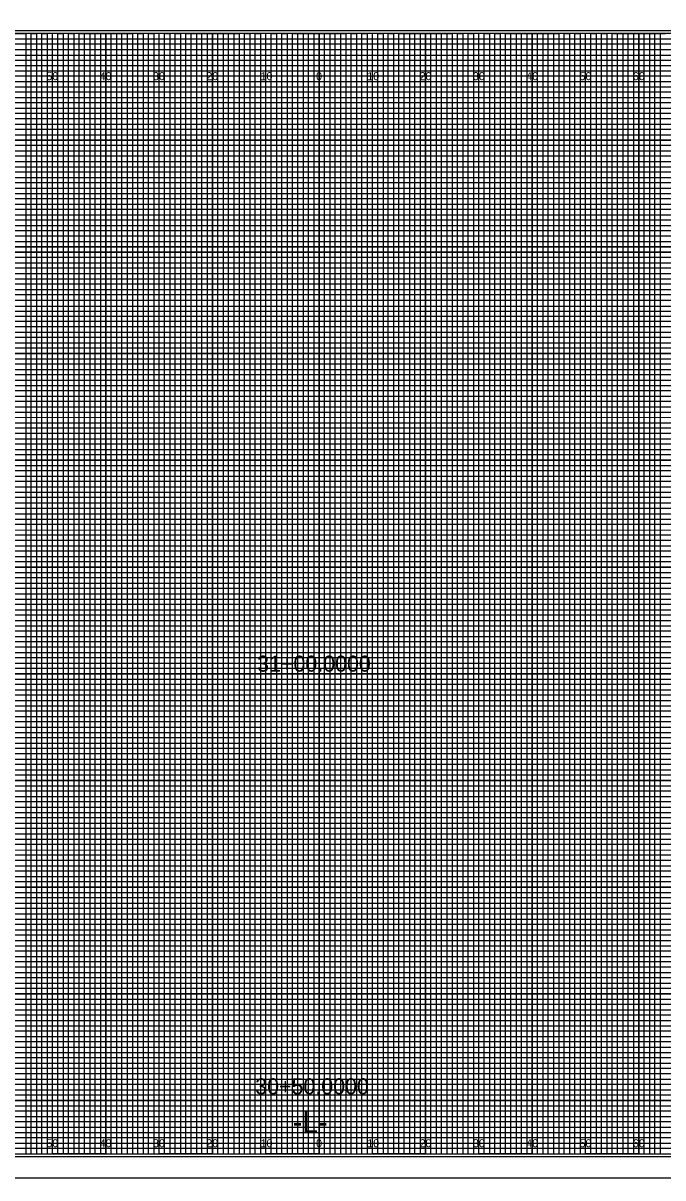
# Model space of a CAD drawing. Extents: x -419 to 4739, y -630 to 13534.
# Drawn here: x 594.1 to 714.1, y 2628 to 2844.5 of the extents above; entities that cross this region are included whole.
import ezdxf

# ---------------------------------------------------------------- set-up
doc = ezdxf.new("R2010")
doc.units = 0
for name, color, linetype in [('Old_Level_62', 7, 'Continuous'), ('Pattern 18', 7, 'Continuous'), ('Pattern 4', 7, 'Continuous'), ('Pattern 5', 7, 'Continuous'), ('Prop Dimension', 7, 'Continuous'), ('Prop Horizontal Alignment', 7, 'Continuous'), ('Prop PHM White Shape', 7, 'Continuous'), ('Raster_Level_0', 7, 'Continuous'), ('Scratch_Level_0', 7, 'Continuous'), ('Scratch_Level_2', 7, 'Continuous'), ('Scratch_Level_3', 7, 'Continuous'), ('Scratch_Level_5', 7, 'Continuous')]:
    doc.layers.add(name, color=color, linetype=linetype)

msp = doc.modelspace()

# ---------------------------------------------------------------- linework, layer by layer
at = {"layer": 'Old_Level_62'}
msp.add_lwpolyline([(809.58, 2842.54), (489.58, 2842.54), (489.58, 2632.54), (809.58, 2632.54)], close=True, dxfattribs=at)
at = {"layer": 'Pattern 18'}
msp.add_lwpolyline([(476.18, 2628.04), (812.88, 2628.04), (812.88, 2847.04), (476.18, 2847.04)], close=True, dxfattribs=at)
at = {"layer": 'Pattern 4'}
for p, q in [((489.58, 2841.54), (749.58, 2841.54)), ((749.58, 2840.52), (489.58, 2840.52)), ((489.58, 2839.54), (749.58, 2839.54)), ((749.58, 2838.43), (489.58, 2838.43)), ((489.58, 2836.54), (809.58, 2836.54))]:
    msp.add_line(p, q, dxfattribs=at)
for points in [[(489.58, 2835.54), (759.58, 2835.54), (809.58, 2835.54), (809.58, 2834.54), (489.58, 2834.54)], [(489.58, 2833.54), (809.58, 2833.54), (809.58, 2831.54), (489.58, 2831.54)], [(489.58, 2830.54), (809.58, 2830.54), (809.58, 2829.54), (489.58, 2829.52)], [(489.58, 2828.54), (809.58, 2828.54), (809.58, 2826.54), (489.58, 2826.54)], [(489.58, 2825.54), (809.58, 2825.54), (809.58, 2824.54), (489.58, 2824.54)], [(489.58, 2823.54), (809.58, 2823.54), (809.58, 2821.54), (489.58, 2821.54)], [(489.58, 2820.54), (809.58, 2820.54), (809.58, 2819.54), (489.58, 2819.54)], [(489.58, 2818.54), (809.58, 2818.54), (809.58, 2816.54), (489.58, 2816.54)], [(489.58, 2815.54), (809.58, 2815.54), (809.58, 2814.54), (489.58, 2814.54)], [(489.58, 2813.54), (809.58, 2813.54), (809.58, 2811.54), (489.58, 2811.54)], [(489.58, 2810.54), (809.58, 2810.54), (809.58, 2809.54), (489.58, 2809.54)], [(489.58, 2808.54), (809.58, 2808.54), (809.58, 2806.49), (809.58, 2805.54), (809.58, 2804.54), (489.58, 2804.54)], [(489.58, 2806.54), (809.58, 2806.54), (809.58, 2805.54), (489.58, 2805.54)], [(489.58, 2803.54), (809.58, 2803.54), (809.58, 2801.54), (489.58, 2801.57)], [(489.58, 2801.57), (809.58, 2801.54), (809.58, 2800.54), (489.58, 2800.54)], [(489.58, 2799.54), (809.58, 2799.54), (809.58, 2798.54), (489.58, 2798.54)], [(489.58, 2796.54), (809.58, 2796.54), (809.58, 2795.54), (489.58, 2795.54)], [(489.58, 2794.54), (809.58, 2794.54), (809.58, 2793.54), (489.58, 2793.54)], [(489.51, 2791.43), (809.58, 2791.43), (809.58, 2790.42), (489.51, 2790.42)], [(489.58, 2789.54), (809.58, 2789.54), (809.58, 2788.54), (489.58, 2788.54)], [(489.58, 2786.54), (809.58, 2786.54), (809.58, 2785.54), (489.58, 2785.54)], [(489.58, 2784.54), (809.58, 2784.54), (809.58, 2783.54), (489.58, 2783.54)], [(489.58, 2781.54), (809.58, 2781.54), (809.58, 2780.54), (489.58, 2780.54)], [(489.58, 2779.54), (809.58, 2779.54), (809.58, 2778.54), (489.58, 2778.54)], [(489.58, 2776.54), (809.58, 2776.54), (809.58, 2775.54), (489.58, 2775.54)], [(489.58, 2774.54), (809.58, 2774.54), (809.58, 2773.54), (489.58, 2773.54)], [(489.58, 2771.54), (809.58, 2771.54), (809.57, 2770.52), (489.58, 2770.54)], [(489.58, 2769.54), (809.58, 2769.54), (809.58, 2768.54), (489.58, 2768.54)], [(489.58, 2766.54), (809.58, 2766.54), (809.58, 2765.54), (489.58, 2765.54)], [(489.58, 2764.54), (809.58, 2764.54), (809.58, 2763.54), (489.58, 2763.54)], [(489.58, 2761.54), (809.58, 2761.54), (809.58, 2760.54), (489.58, 2760.54)], [(489.58, 2759.54), (809.58, 2759.54), (809.58, 2758.54), (489.58, 2758.54)], [(489.58, 2756.54), (809.58, 2756.54), (809.58, 2755.54), (489.58, 2755.54)], [(489.58, 2754.54), (809.58, 2754.54), (809.58, 2753.54), (489.58, 2753.54)], [(489.58, 2751.54), (809.58, 2751.54), (809.58, 2750.54), (489.58, 2750.54)], [(489.58, 2749.53), (809.65, 2749.45), (809.58, 2748.54), (489.58, 2748.54)], [(489.58, 2746.54), (809.58, 2746.54), (809.58, 2745.54), (489.58, 2745.54)], [(489.58, 2744.54), (809.58, 2744.54), (809.58, 2743.54), (489.58, 2743.54)], [(489.58, 2741.54), (809.58, 2741.54), (809.58, 2740.54), (489.58, 2740.54)], [(489.58, 2739.54), (809.58, 2739.54), (809.58, 2738.54), (489.58, 2738.54)], [(489.58, 2736.54), (809.58, 2736.54), (809.58, 2735.54), (489.58, 2735.54)], [(489.58, 2734.54), (809.58, 2734.54), (809.58, 2733.54), (489.58, 2733.54)], [(489.58, 2731.54), (809.58, 2731.54), (809.58, 2730.54), (489.58, 2730.54)], [(489.58, 2729.54), (809.58, 2729.54), (809.58, 2728.54), (489.58, 2728.54)], [(489.58, 2726.54), (809.58, 2726.54), (809.58, 2725.54), (489.58, 2725.54)], [(489.58, 2724.54), (809.58, 2724.54), (809.58, 2723.54), (489.58, 2723.54)], [(489.58, 2721.54), (809.58, 2721.54), (809.58, 2720.54), (489.58, 2720.54)], [(489.58, 2719.54), (809.58, 2719.54), (809.58, 2718.54), (489.58, 2718.54)], [(489.58, 2716.54), (809.58, 2716.54), (809.58, 2715.54), (489.58, 2715.54)], [(489.58, 2714.54), (809.58, 2714.54), (809.58, 2713.54), (489.58, 2713.54)], [(489.58, 2711.54), (809.58, 2711.54), (809.57, 2710.52), (489.58, 2710.54)], [(489.58, 2709.54), (809.58, 2709.54), (809.58, 2708.54), (489.58, 2708.54)], [(489.58, 2706.54), (809.58, 2706.54), (809.58, 2705.54), (489.58, 2705.54)], [(489.58, 2704.54), (809.58, 2704.54), (809.58, 2703.54), (489.58, 2703.54)], [(489.58, 2701.54), (809.58, 2701.54), (809.58, 2700.54), (489.58, 2700.54)], [(489.58, 2699.54), (809.58, 2699.54), (809.58, 2698.54), (489.58, 2698.54)], [(489.58, 2696.54), (809.58, 2696.54), (809.58, 2695.54), (489.58, 2695.54)], [(489.58, 2694.54), (809.58, 2694.54), (809.58, 2693.54), (489.58, 2693.54)], [(489.58, 2691.54), (809.58, 2691.54), (809.58, 2690.54), (489.58, 2690.54)], [(489.58, 2689.53), (809.65, 2689.45), (809.58, 2688.54), (489.58, 2688.54)], [(489.58, 2686.54), (809.58, 2686.54), (809.58, 2685.54), (489.58, 2685.54)], [(489.58, 2684.54), (809.58, 2684.54), (809.58, 2683.54), (489.58, 2683.54)], [(489.58, 2681.54), (809.58, 2681.54), (809.58, 2680.54), (489.58, 2680.54)], [(489.58, 2679.54), (809.58, 2679.54), (809.58, 2678.54), (489.58, 2678.54)], [(489.58, 2676.54), (809.58, 2676.54), (809.58, 2675.54), (489.58, 2675.54)], [(489.58, 2674.54), (809.58, 2674.54), (809.58, 2673.54), (489.58, 2673.54)], [(489.58, 2671.54), (809.58, 2671.54), (809.58, 2670.54), (489.58, 2670.54)], [(489.58, 2669.54), (809.58, 2669.54), (809.58, 2668.54), (489.58, 2668.54)], [(489.58, 2666.54), (809.58, 2666.54), (809.58, 2665.54), (489.58, 2665.54)], [(489.58, 2664.54), (809.58, 2664.54), (809.58, 2663.54), (489.58, 2663.54)], [(489.58, 2661.54), (809.58, 2661.54), (809.58, 2660.54), (489.58, 2660.54)], [(489.58, 2659.54), (809.58, 2659.54), (809.58, 2658.54), (489.58, 2658.54)], [(489.58, 2656.54), (809.58, 2656.54), (809.58, 2655.54), (489.58, 2655.54)], [(489.58, 2654.54), (809.58, 2654.54), (809.58, 2653.54), (489.58, 2653.54)], [(489.58, 2651.54), (809.58, 2651.54), (809.58, 2650.54), (489.58, 2650.54)], [(489.58, 2649.54), (809.58, 2649.54), (809.58, 2648.54), (489.58, 2648.54)], [(489.58, 2646.54), (809.58, 2646.54), (809.58, 2645.54), (489.58, 2645.54)], [(489.58, 2644.54), (809.58, 2644.54), (809.58, 2643.54), (489.58, 2643.54)], [(489.58, 2641.54), (809.58, 2641.54), (809.58, 2640.54), (489.58, 2640.54)], [(489.58, 2639.54), (809.58, 2639.54), (809.58, 2638.54), (489.58, 2638.54)], [(489.58, 2636.54), (809.58, 2636.54), (809.58, 2635.54), (489.58, 2635.54)], [(489.58, 2634.54), (809.58, 2634.54), (809.58, 2633.54), (489.58, 2633.54)]]:
    msp.add_lwpolyline(points, dxfattribs=at)
at = {"layer": 'Pattern 5'}
msp.add_line((476.18, 2628.04), (812.88, 2628.04), dxfattribs=at)
at = {"layer": 'Prop Dimension'}
for points in [[(594.58, 2632.54), (595.58, 2632.54), (595.58, 2842.54), (596.58, 2842.54), (596.58, 2632.54)], [(596.58, 2632.54), (597.58, 2632.54), (597.58, 2842.54), (598.58, 2842.54), (598.58, 2632.54)], [(599.58, 2632.54), (600.58, 2632.54), (600.58, 2842.54), (601.58, 2842.54), (601.58, 2632.54)], [(601.58, 2632.54), (602.58, 2632.54), (602.58, 2842.54), (603.58, 2842.54), (603.58, 2632.54)], [(604.58, 2632.54), (605.58, 2632.54), (605.58, 2842.54), (606.58, 2842.54), (606.58, 2632.54)], [(606.58, 2632.54), (607.58, 2632.54), (607.58, 2842.54), (608.58, 2842.54), (608.58, 2632.54)], [(609.58, 2632.54), (610.58, 2632.54), (610.58, 2842.54), (611.58, 2842.54), (611.58, 2632.54)], [(611.58, 2632.54), (612.58, 2632.54), (612.58, 2842.54), (613.58, 2842.54), (613.58, 2632.54)], [(614.58, 2632.54), (615.58, 2632.54), (615.58, 2842.54), (616.58, 2842.54), (616.58, 2632.54)], [(616.58, 2632.54), (617.58, 2632.54), (617.58, 2842.54), (618.58, 2842.54), (618.58, 2632.54)], [(619.58, 2632.54), (620.58, 2632.54), (620.58, 2842.54), (621.58, 2842.54), (621.58, 2632.54)], [(621.58, 2632.54), (622.58, 2632.54), (622.58, 2842.54), (623.58, 2842.54), (623.58, 2632.54)], [(624.58, 2632.54), (625.58, 2632.54), (625.58, 2842.54), (626.58, 2842.54), (626.58, 2632.54)], [(626.58, 2632.54), (627.58, 2632.54), (627.58, 2842.54), (628.58, 2842.54), (628.58, 2632.54)], [(629.58, 2632.54), (630.58, 2632.54), (630.58, 2842.54), (631.58, 2842.54), (631.58, 2632.54)], [(631.58, 2632.54), (632.58, 2632.54), (632.58, 2842.54), (633.58, 2842.54), (633.58, 2632.54)], [(634.58, 2632.54), (635.58, 2632.54), (635.58, 2842.54), (636.58, 2842.54), (636.58, 2632.54)], [(636.58, 2632.54), (637.58, 2632.54), (637.58, 2842.54), (638.58, 2842.54), (638.58, 2632.54)], [(639.58, 2632.54), (640.58, 2632.54), (640.58, 2842.54), (641.58, 2842.54), (641.58, 2632.54)], [(641.58, 2632.54), (642.58, 2632.54), (642.58, 2842.54), (643.58, 2842.54), (643.58, 2632.54)], [(644.58, 2632.54), (645.58, 2632.54), (645.58, 2842.54), (646.58, 2842.54), (646.58, 2632.54)], [(646.58, 2632.54), (647.58, 2632.54), (647.58, 2842.54), (648.58, 2842.54), (648.58, 2632.54)], [(649.58, 2632.54), (650.58, 2632.54), (650.58, 2842.54), (651.58, 2842.54), (651.58, 2632.54)], [(651.58, 2632.54), (652.58, 2632.54), (652.58, 2842.54), (653.58, 2842.54), (653.58, 2632.54)], [(654.58, 2632.54), (655.58, 2632.54), (655.58, 2842.54), (656.58, 2842.54), (656.58, 2632.54)], [(656.58, 2632.54), (657.58, 2632.54), (657.58, 2842.54), (658.58, 2842.54), (658.58, 2632.54)], [(659.58, 2632.54), (660.58, 2632.54), (660.58, 2842.54), (661.58, 2842.54), (661.58, 2632.54)], [(661.58, 2632.54), (662.58, 2632.54), (662.58, 2842.54), (663.58, 2842.54), (663.58, 2632.54)], [(664.58, 2632.54), (665.58, 2632.54), (665.58, 2842.54), (666.58, 2842.54), (666.58, 2632.54)], [(666.58, 2632.54), (667.58, 2632.54), (667.58, 2842.54), (668.58, 2842.54), (668.58, 2632.54)], [(669.58, 2632.54), (670.58, 2632.54), (670.58, 2842.54), (671.58, 2842.54), (671.58, 2632.54)], [(671.58, 2632.54), (672.58, 2632.54), (672.58, 2842.54), (673.58, 2842.54), (673.58, 2632.54)], [(674.58, 2632.54), (675.58, 2632.54), (675.58, 2842.54), (676.58, 2842.54), (676.58, 2632.54)], [(676.58, 2632.54), (677.58, 2632.54), (677.58, 2842.54), (678.58, 2842.54), (678.58, 2632.54)], [(679.58, 2632.54), (680.58, 2632.54), (680.58, 2842.54), (681.58, 2842.54), (681.58, 2632.54)], [(681.58, 2632.54), (682.58, 2632.54), (682.58, 2842.54), (683.58, 2842.54), (683.58, 2632.54)], [(684.58, 2632.54), (685.58, 2632.54), (685.58, 2842.54), (686.58, 2842.54), (686.58, 2632.54)], [(686.58, 2632.54), (687.58, 2632.54), (687.58, 2842.54), (688.58, 2842.54), (688.58, 2632.54)], [(689.58, 2632.54), (690.58, 2632.54), (690.58, 2842.54), (691.58, 2842.54), (691.58, 2632.54)], [(691.58, 2632.54), (692.58, 2632.54), (692.58, 2842.54), (693.58, 2842.54), (693.58, 2632.54)], [(694.58, 2632.54), (695.58, 2632.54), (695.58, 2842.54), (696.58, 2842.54), (696.58, 2632.54)], [(696.58, 2632.54), (697.58, 2632.54), (697.58, 2842.54), (698.58, 2842.54), (698.58, 2632.54)], [(699.58, 2632.54), (700.58, 2632.54), (700.58, 2842.54), (701.58, 2842.54), (701.58, 2632.54)], [(701.58, 2632.54), (702.58, 2632.54), (702.58, 2842.54), (703.58, 2842.54), (703.58, 2632.54)], [(704.58, 2632.54), (705.58, 2632.54), (705.58, 2842.54), (706.58, 2842.54), (706.58, 2632.54)], [(706.58, 2632.54), (707.58, 2632.54), (707.58, 2842.54), (708.58, 2842.54), (708.58, 2632.54)], [(709.58, 2632.54), (710.58, 2632.54), (710.58, 2842.54), (711.58, 2842.54), (711.58, 2632.54)], [(711.58, 2632.54), (712.58, 2632.54), (712.58, 2842.54), (713.58, 2842.54), (713.58, 2632.54)]]:
    msp.add_lwpolyline(points, dxfattribs=at)
at = {"layer": 'Prop Horizontal Alignment'}
for points in [[(584.58, 2842.54), (594.58, 2842.54), (594.58, 2632.54), (604.58, 2632.54), (604.58, 2842.54), (614.58, 2842.54), (614.58, 2632.54), (624.58, 2632.54), (624.58, 2842.54), (634.58, 2842.54), (634.58, 2632.54), (644.58, 2632.54), (644.58, 2842.54), (654.58, 2842.54), (654.58, 2632.54), (664.58, 2632.54), (664.58, 2842.54), (674.58, 2842.54), (674.58, 2632.54), (684.58, 2632.54), (684.58, 2842.54), (694.58, 2842.54), (694.58, 2632.54), (704.58, 2632.54), (704.58, 2842.54), (714.58, 2842.54)], [(489.58, 2837.54), (764.58, 2837.54)], [(489.58, 2817.54), (809.58, 2817.54), (809.58, 2827.54), (489.58, 2827.54)], [(489.58, 2797.54), (809.58, 2797.54), (809.58, 2807.54), (489.58, 2807.54)], [(489.58, 2777.54), (809.58, 2777.54), (809.58, 2787.54), (489.58, 2787.54)], [(489.58, 2757.54), (809.58, 2757.54), (809.58, 2767.54), (489.58, 2767.54)], [(489.58, 2737.54), (809.58, 2737.54), (809.58, 2747.54), (489.58, 2747.54)], [(489.58, 2717.54), (809.58, 2717.54), (809.58, 2727.54), (489.58, 2727.54)], [(489.58, 2697.54), (809.58, 2697.54), (809.58, 2707.54), (489.58, 2707.54)], [(489.58, 2677.54), (809.58, 2677.54), (809.58, 2687.54), (489.58, 2687.54)], [(489.58, 2657.54), (809.58, 2657.54), (809.58, 2667.54), (489.58, 2667.54)], [(489.58, 2637.54), (809.58, 2637.54), (809.58, 2647.54), (489.58, 2647.54)]]:
    msp.add_lwpolyline(points, dxfattribs=at)
at = {"layer": 'Scratch_Level_0'}
for p, q in [((599.58, 2632.54), (599.58, 2842.54)), ((609.58, 2632.54), (609.58, 2842.54)), ((619.58, 2632.54), (619.58, 2842.54)), ((629.58, 2632.54), (629.58, 2842.54)), ((639.58, 2632.54), (639.58, 2842.54)), ((649.58, 2632.54), (649.58, 2842.54)), ((659.58, 2632.54), (659.58, 2842.54)), ((669.58, 2632.54), (669.58, 2842.54)), ((679.58, 2632.54), (679.58, 2842.54)), ((689.58, 2632.54), (689.58, 2842.54)), ((699.58, 2632.54), (699.58, 2842.54)), ((709.58, 2632.54), (709.58, 2842.54)), ((489.58, 2832.54), (809.58, 2832.54)), ((489.58, 2822.54), (809.58, 2822.54)), ((489.58, 2812.54), (809.58, 2812.54)), ((489.58, 2802.54), (809.58, 2802.54)), ((489.58, 2792.54), (809.58, 2792.54)), ((489.58, 2782.54), (809.58, 2782.54)), ((489.58, 2772.54), (809.58, 2772.54)), ((489.58, 2762.54), (809.58, 2762.54)), ((489.58, 2752.54), (809.58, 2752.54)), ((489.58, 2742.54), (809.58, 2742.54)), ((489.58, 2732.54), (809.58, 2732.54)), ((489.58, 2722.54), (809.58, 2722.54)), ((489.58, 2712.54), (809.58, 2712.54)), ((489.58, 2702.54), (809.58, 2702.54)), ((489.58, 2692.54), (809.58, 2692.54)), ((489.58, 2682.54), (809.58, 2682.54)), ((489.58, 2672.54), (809.58, 2672.54)), ((489.58, 2662.54), (809.58, 2662.54)), ((489.58, 2652.54), (809.58, 2652.54)), ((489.58, 2642.54), (809.58, 2642.54))]:
    msp.add_line(p, q, dxfattribs=at)
at = {"layer": 'Scratch_Level_3'}
for p, q in [((599.58, 2842.54), (589.58, 2842.54)), ((599.58, 2632.54), (599.58, 2842.54)), ((619.58, 2842.54), (609.58, 2842.54)), ((609.58, 2842.54), (609.58, 2632.54)), ((619.58, 2632.54), (619.58, 2842.54)), ((639.58, 2842.54), (629.58, 2842.54)), ((629.58, 2842.54), (629.58, 2632.54)), ((639.58, 2632.54), (639.58, 2842.54)), ((659.58, 2842.54), (649.58, 2842.54)), ((649.58, 2842.54), (649.58, 2632.54)), ((659.58, 2632.54), (659.58, 2842.54)), ((679.58, 2842.54), (669.58, 2842.54)), ((669.58, 2842.54), (669.58, 2632.54)), ((679.58, 2632.54), (679.58, 2842.54)), ((699.58, 2842.54), (689.58, 2842.54)), ((689.58, 2842.54), (689.58, 2632.54)), ((699.58, 2632.54), (699.58, 2842.54)), ((719.58, 2842.54), (709.58, 2842.54)), ((709.58, 2842.54), (709.58, 2632.54)), ((609.58, 2632.54), (599.58, 2632.54)), ((629.58, 2632.54), (619.58, 2632.54)), ((649.58, 2632.54), (639.58, 2632.54)), ((669.58, 2632.54), (659.58, 2632.54)), ((689.58, 2632.54), (679.58, 2632.54)), ((709.58, 2632.54), (699.58, 2632.54))]:
    msp.add_line(p, q, dxfattribs=at)
for points in [[(489.58, 2832.54), (809.58, 2832.54), (809.58, 2822.54), (489.58, 2822.54)], [(489.58, 2812.54), (809.58, 2812.54), (809.58, 2802.54), (489.58, 2802.54)], [(489.58, 2792.54), (809.58, 2792.54), (809.58, 2782.54), (489.58, 2782.54)], [(489.58, 2772.54), (809.58, 2772.54), (809.58, 2762.54), (489.58, 2762.54)], [(489.58, 2752.54), (809.58, 2752.54), (809.58, 2742.54), (489.58, 2742.54)], [(489.58, 2732.54), (809.58, 2732.54), (809.58, 2722.54), (489.58, 2722.54)], [(489.58, 2712.54), (809.58, 2712.54), (809.58, 2702.54), (489.58, 2702.54)], [(489.58, 2692.54), (809.58, 2692.54), (809.58, 2682.54), (489.58, 2682.54)], [(489.58, 2672.54), (809.58, 2672.54), (809.58, 2662.54), (489.58, 2662.54)], [(489.58, 2652.54), (809.58, 2652.54), (809.58, 2642.54), (489.58, 2642.54)]]:
    msp.add_lwpolyline(points, dxfattribs=at)
at = {"layer": 'Scratch_Level_5'}
msp.add_lwpolyline([(478.78, 2632.04), (811.98, 2632.04), (811.98, 2843.04), (478.78, 2843.04)], close=True, dxfattribs=at)

# ---------------------------------------------------------------- texts
at = {"layer": 'Prop PHM White Shape'}
msp.add_text('-L-', height=4, dxfattribs=at).set_placement((644.64, 2636.54))
at = {"layer": 'Raster_Level_0'}
for s, p in [('50', (598.44, 2833.79)), ('40', (608.44, 2833.79)), ('30', (618.44, 2833.79)), ('20', (628.44, 2833.79)), ('10', (638.62, 2833.79)), ('0', (649.03, 2833.79)), ('0', (649.03, 2833.79)), ('10', (658.62, 2833.79)), ('20', (668.44, 2833.79)), ('30', (678.44, 2833.79)), ('40', (688.44, 2833.79)), ('50', (698.44, 2833.79)), ('60', (708.44, 2833.79)), ('50', (598.44, 2633.79)), ('40', (608.44, 2633.79)), ('30', (618.44, 2633.79)), ('20', (628.44, 2633.79)), ('10', (638.62, 2633.79)), ('0', (649.03, 2633.79)), ('0', (649.03, 2633.79)), ('10', (658.62, 2633.79)), ('20', (668.44, 2633.79)), ('30', (678.44, 2633.79)), ('40', (688.44, 2633.79)), ('50', (698.44, 2633.79)), ('60', (708.44, 2633.79))]:
    msp.add_text(s, height=1.5, dxfattribs=at).set_placement(p)
at = {"layer": 'Scratch_Level_2'}
for s, p in [('31+00.0000', (637.98, 2722.93)), ('30+50.0000', (637.62, 2643.71))]:
    msp.add_text(s, height=3, dxfattribs=at).set_placement(p)

doc.saveas('drawing.dxf')
